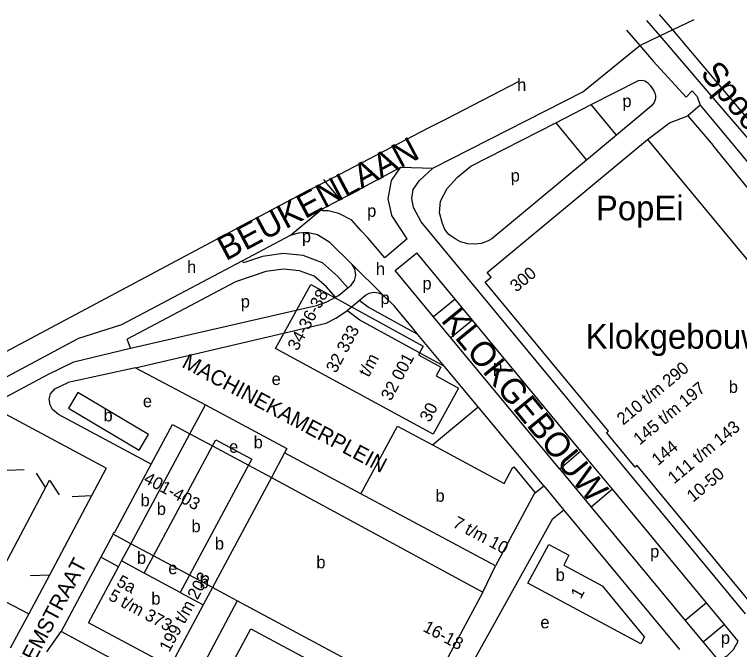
# Model space of a CAD drawing. Extents: x 159261 to 160849, y 382514 to 384534.
# Drawn here: x 159684.3 to 159920.1, y 384327.5 to 384534 of the extents above; entities that cross this region are included whole.
import ezdxf

# ---------------------------------------------------------------- set-up
doc = ezdxf.new("R2010")
doc.units = 0
for name, color, linetype in [('BLT_Basislijn', 7, 'Continuous'), ('BLT_Bebouwing', 7, 'Continuous'), ('BLT_Bebouwing_beschrifting', 7, 'Continuous'), ('BLT_Centroide', 7, 'Continuous'), ('BLT_Huisnummer', 7, 'Continuous'), ('BLT_Huisnummer_reeks', 7, 'Continuous'), ('BLT_Huisnummer_zonder_bebouwing', 7, 'Continuous'), ('BLT_Onderdoorgang_en_onderverdeling', 7, 'Continuous'), ('BLT_Plantopo', 7, 'Continuous'), ('BLT_Spoorlijn', 7, 'Continuous'), ('BLT_Straatnaam', 7, 'Continuous'), ('BLT_Straatnaam_hoofdweg', 7, 'Continuous'), ('BLT_Vlakafsluiter', 7, 'Continuous'), ('BLT_Waternaam_spoorwegen', 7, 'Continuous')]:
    doc.layers.add(name, color=color, linetype=linetype)

msp = doc.modelspace()

# ---------------------------------------------------------------- linework, layer by layer
at = {"layer": 'BLT_Basislijn'}
for p, q in [((159883.3, 384528.96), (159887.62, 384523.99)), ((159887.62, 384523.99), (159888.83, 384522.59)), ((159888.83, 384522.59), (159892.14, 384518.77)), ((159880.06, 384494.81), (159871.83, 384504.71)), ((159907.31, 384504.59), (159903.26, 384501.09)), ((159818.97, 384497.14), (159824.51, 384500)), ((159903.26, 384501.09), (159911.54, 384491.41)), ((159860.3, 384498.83), (159870.32, 384486.71)), ((159890.13, 384493.38), (159897.29, 384498.77)), ((159992.65, 384391.11), (159911.54, 384491.41)), ((159812, 384461.06), (159807.01, 384468.71)), ((159773.89, 384462.18), (159758.39, 384453.97)), ((159812, 384461.06), (159804.69, 384454.93)), ((159808.04, 384450.73), (159815.18, 384456.48)), ((159758.39, 384453.97), (159719.12, 384433.16)), ((159756.13, 384447.11), (159720.88, 384428.43)), ((159807.85, 384439.21), (159804.11, 384442.9)), ((159792.42, 384437.79), (159796.34, 384441.01)), ((159827.63, 384441.43), (159820.56, 384435.66)), ((159813.7, 384432.18), (159807.85, 384439.21)), ((159719.12, 384433.16), (159704.82, 384428.52)), ((159833.28, 384434.61), (159826.21, 384428.85)), ((159815.5, 384430), (159813.7, 384432.18)), ((159721.97, 384425.49), (159720.88, 384428.43)), ((159824.16, 384419.58), (159815.5, 384430)), ((159723.61, 384419.14), (159701.77, 384414.33)), ((159723.61, 384419.14), (159746.36, 384407.13)), ((159835.03, 384406.49), (159824.16, 384419.58)), ((159820.19, 384394.08), (159835.03, 384406.49)), ((159856.39, 384380.76), (159835.03, 384406.49)), ((159714.14, 384386.52), (159681.37, 384404.11)), ((159796.96, 384378.15), (159772.09, 384391.47)), ((159868.52, 384392.02), (159861.67, 384386.16)), ((159681.86, 384385.8), (159687.42, 384386.08)), ((159714.14, 384386.52), (159709.34, 384377.49)), ((159691.37, 384384.93), (159694.31, 384380.06)), ((159878.72, 384379.69), (159871.87, 384373.84)), ((159709.34, 384377.49), (159695.62, 384351.7)), ((159709.34, 384377.49), (159703.07, 384377.2)), ((159716.34, 384365.05), (159712.39, 384357.56)), ((159712.39, 384357.56), (159711.63, 384356.15)), ((159718.12, 384354.46), (159712.39, 384357.56)), ((159711.63, 384356.15), (159699.41, 384333.4)), ((159659.71, 384354.41), (159688.92, 384339.09)), ((159836.63, 384346.17), (159840.7, 384354.72)), ((159695.62, 384351.7), (159688.92, 384339.09)), ((159695.62, 384351.7), (159689.42, 384351.51)), ((159756.68, 384343.41), (159739.89, 384311.64)), ((159909.34, 384342.69), (159902.45, 384336.95)), ((159688.92, 384339.09), (159682.9, 384327.94)), ((159915.17, 384335.64), (159908.3, 384329.89)), ((159694.8, 384326.79), (159699.41, 384333.4)), ((159739.89, 384311.64), (159699.41, 384333.4))]:
    msp.add_line(p, q, dxfattribs=at)
for points in [[(159820.29, 384484.04), (159869.1, 384508.93), (159887.62, 384523.99)], [(159892.14, 384518.77), (159902.68, 384507.17), (159904.71, 384509.2), (159906.26, 384507.41), (159907.31, 384504.59)], [(159824.51, 384500), (159848.42, 384512.35)], [(159871.83, 384504.71), (159887.27, 384512.58)], [(159887.27, 384512.58), (159888.36, 384512.68), (159889.31, 384512.43), (159890.16, 384511.89), (159890.98, 384510.99), (159892.06, 384509.44), (159892.55, 384508.43), (159892.7, 384507.6), (159892.7, 384506.8), (159892.58, 384506.05), (159892.3, 384505.39), (159891.33, 384504.18), (159880.06, 384494.81)], [(159860.3, 384498.83), (159871.83, 384504.71)], [(159907.31, 384504.59), (159911.11, 384500)], [(159911.11, 384500), (159915.56, 384494.64)], [(159785.34, 384479.66), (159818.97, 384497.14)], [(159832.66, 384484.74), (159860.3, 384498.83)], [(159880.06, 384494.81), (159870.32, 384486.71)], [(159915.56, 384494.64), (159942.2, 384462.5), (159986.64, 384408.89), (159997.83, 384395.4)], [(159870.32, 384486.71), (159839.52, 384461.11), (159838.72, 384460.63), (159837.6, 384460.11), (159836.05, 384459.6), (159834.12, 384459.32), (159831.67, 384459.42), (159829.36, 384460.05), (159827.62, 384461.06), (159825.58, 384462.53), (159824.28, 384464.07), (159823.44, 384466.11), (159822.51, 384469.48), (159822.79, 384473.34), (159824.96, 384477.49), (159828.31, 384481.17), (159832.66, 384484.74)], [(159790.15, 384473.89), (159809.93, 384484.37)], [(159807.01, 384468.71), (159806.99, 384468.74), (159805.82, 384474.06), (159806.9, 384480.06), (159809.93, 384484.37)], [(159823.77, 384457.87), (159816.51, 384466.64), (159814.1, 384471.31), (159813.47, 384474.2), (159813.99, 384477.11), (159816.02, 384480), (159820.29, 384484.04)], [(159660.14, 384413.06), (159774.28, 384473.91), (159785.34, 384479.66)], [(159784.19, 384470.73), (159790.15, 384473.89)], [(159797.08, 384463.72), (159793.96, 384467.17), (159789.78, 384469.33), (159786.25, 384470.18), (159784.52, 384470.18), (159784.19, 384470.73)], [(159804.69, 384454.93), (159799.3, 384461.26), (159797.08, 384463.72)], [(159779.37, 384463.11), (159776.51, 384462.93), (159773.89, 384462.18)], [(159794.14, 384452.72), (159786.83, 384459.92), (159782.87, 384462.33), (159779.37, 384463.11)], [(159827.63, 384441.43), (159815.18, 384456.48)], [(159922.02, 384339.13), (159823.77, 384457.87)], [(159792.65, 384445.12), (159789.28, 384448.98), (159784.4, 384453.31), (159778.14, 384455.63), (159771.67, 384456.29), (159764.92, 384455.38), (159758.75, 384453.28), (159758.39, 384453.97)], [(159792.65, 384445.12), (159793.73, 384446.02), (159794.88, 384447.57), (159795.28, 384449.29), (159795.01, 384451.27), (159794.14, 384452.72)], [(159788.65, 384442.1), (159785.72, 384445.45), (159781.79, 384448.95), (159777, 384450.72), (159771.75, 384451.26), (159766.07, 384450.49), (159756.13, 384447.11)], [(159820.56, 384435.66), (159808.04, 384450.73)], [(159788.65, 384442.1), (159789.65, 384442.64), (159792.65, 384445.12)], [(159796.34, 384441.01), (159798.45, 384442.75), (159799.67, 384443.43), (159801.15, 384443.73), (159802.61, 384443.57), (159804.11, 384442.9)], [(159721.97, 384425.49), (159782.48, 384439.42), (159785.82, 384440.58), (159788.65, 384442.1)], [(159815.5, 384430), (159799.27, 384438.86), (159796.34, 384441.01)], [(159833.28, 384434.61), (159827.63, 384441.43)], [(159723.61, 384419.14), (159785.69, 384433.68), (159788.75, 384435.28), (159791.64, 384437.15), (159792.42, 384437.79)], [(159824.16, 384419.58), (159796.59, 384434.63), (159792.67, 384437.51), (159792.42, 384437.79)], [(159826.21, 384428.85), (159820.56, 384435.66)], [(159868.52, 384392.02), (159833.28, 384434.61)], [(159662.21, 384405.78), (159704.82, 384428.52)], [(159861.67, 384386.16), (159826.21, 384428.85)], [(159579.36, 384354.97), (159695.11, 384417), (159703.57, 384421.08), (159721.97, 384425.49)], [(159728.73, 384387.76), (159698.64, 384403.92), (159696.65, 384405.62), (159695.92, 384407.15), (159695.6, 384408.95), (159696.04, 384410.72), (159697.35, 384412.25), (159701.77, 384414.33)], [(159878.72, 384379.69), (159868.52, 384392.02)], [(159861.67, 384386.15), (159871.87, 384373.84)], [(159680.99, 384354.8), (159695.68, 384382.55), (159698.84, 384377.82)], [(159853.65, 384378.49), (159856.39, 384380.76)], [(159909.34, 384342.69), (159878.72, 384379.69)], [(159862.97, 384372.83), (159859.15, 384369.78), (159831.21, 384319.52)], [(159862.97, 384372.83), (159900.54, 384327.5)], [(159871.87, 384373.84), (159902.45, 384336.95)], [(159915.17, 384335.64), (159909.34, 384342.69)], [(159902.45, 384336.95), (159908.3, 384329.89)], [(159919.61, 384330.28), (159915.17, 384335.64)], [(159908.3, 384329.89), (159913.1, 384324.1)], [(159913.1, 384324.1), (159916.05, 384325.43), (159918.17, 384327.51), (159919.61, 384330.28)]]:
    msp.add_lwpolyline(points, dxfattribs=at)
at = {"layer": 'BLT_Bebouwing'}
for p, q in [((159741.29, 384397.67), (159746.36, 384407.13)), ((159728.73, 384387.76), (159735.7, 384400.71)), ((159735.7, 384400.71), (159741.29, 384397.67)), ((159722.1, 384361.89), (159741.29, 384397.67)), ((159729.46, 384357.96), (159748.69, 384393.74)), ((159748.69, 384393.74), (159760.41, 384387.46)), ((159772.09, 384391.47), (159767.81, 384383.48)), ((159760.41, 384387.46), (159741.21, 384351.68)), ((159767.81, 384383.48), (159748.65, 384347.7)), ((159767.81, 384383.48), (159836.63, 384346.17)), ((159722.1, 384361.89), (159716.34, 384365.05)), ((159719.11, 384356.32), (159722.1, 384361.89)), ((159726.46, 384352.38), (159729.46, 384357.96)), ((159741.21, 384351.68), (159729.46, 384357.96)), ((159718.12, 384354.46), (159719.11, 384356.32)), ((159738.21, 384346.1), (159726.46, 384352.38)), ((159741.21, 384351.68), (159738.21, 384346.1)), ((159889.19, 384331.68), (159875.6, 384348.17)), ((159748.65, 384347.7), (159745.65, 384342.11)), ((159756.68, 384343.41), (159748.65, 384347.7)), ((159836.63, 384346.17), (159817.59, 384310.79)), ((159817.59, 384310.79), (159756.68, 384343.41)), ((159745.65, 384342.11), (159744.63, 384340.2))]:
    msp.add_line(p, q, dxfattribs=at)
for points in [[(159837.38, 384446.95), (159839.29, 384448.56), (159837.99, 384450.14), (159890.13, 384493.38)], [(159890.13, 384493.38), (159982.21, 384382.41)], [(159928.03, 384337.56), (159886.79, 384387.35), (159886.17, 384386.84), (159876.87, 384398.07), (159877.5, 384398.55), (159837.38, 384446.95)], [(159746.36, 384407.13), (159772.85, 384392.87), (159772.09, 384391.47)], [(159840.7, 384354.72), (159796.96, 384378.15), (159808.8, 384400.21)], [(159808.8, 384400.21), (159820.19, 384394.08)], [(159748.69, 384393.74), (159749.76, 384395.71), (159761.46, 384389.44), (159760.41, 384387.46)], [(159820.19, 384394.08), (159843.58, 384381.5), (159846.26, 384386.64), (159846.65, 384386.97), (159853.65, 384378.49)], [(159716.34, 384365.05), (159716.72, 384365.76), (159716.86, 384365.69), (159728.73, 384387.76)], [(159853.65, 384378.49), (159853.29, 384378.19), (159840.7, 384354.72)], [(159851.21, 384349.09), (159858.11, 384361.67), (159864.61, 384358.17), (159862.89, 384354.97), (159875.6, 384348.17)], [(159744.63, 384340.2), (159734.86, 384321.96), (159708.32, 384336.18), (159718.12, 384354.46)], [(159889.19, 384331.68), (159887.99, 384329.43), (159851.21, 384349.09)]]:
    msp.add_lwpolyline(points, dxfattribs=at)
msp.add_lwpolyline([(159704.88, 384411.09), (159701.85, 384405.99), (159724.8, 384392.36), (159727.83, 384397.47)], close=True, dxfattribs=at)
at = {"layer": 'BLT_Onderdoorgang_en_onderverdeling'}
for p, q in [((159741.29, 384397.67), (159748.69, 384393.74)), ((159760.41, 384387.46), (159767.81, 384383.48)), ((159729.46, 384357.96), (159722.1, 384361.89)), ((159726.46, 384352.38), (159719.11, 384356.32)), ((159748.65, 384347.7), (159741.21, 384351.68)), ((159738.21, 384346.1), (159745.65, 384342.11))]:
    msp.add_line(p, q, dxfattribs=at)
at = {"layer": 'BLT_Plantopo'}
for points in [[(159769.19, 384425.37), (159780.61, 384446.25), (159817.23, 384426.21), (159815.69, 384423.4), (159822.99, 384419.4), (159821.41, 384416.51), (159828.65, 384412.55), (159820.48, 384397.52)], [(159761.12, 384334.25), (159813.05, 384306.37), (159801.06, 384284.04), (159749.13, 384311.92)]]:
    msp.add_lwpolyline(points, close=True, dxfattribs=at)
at = {"layer": 'BLT_Spoorlijn'}
for p, q in [((159889.83, 384532.07), (159894.12, 384527.06)), ((159898.24, 384529.01), (159922.83, 384500)), ((159894.12, 384527.06), (159915.97, 384501.58))]:
    msp.add_line(p, q, dxfattribs=at)
for points in [[(159893.95, 384534.03), (159896.83, 384530.68), (159898.24, 384529.01)], [(159915.97, 384501.58), (159917.34, 384500)], [(159917.34, 384500), (159975.81, 384432.34)]]:
    msp.add_lwpolyline(points, dxfattribs=at)
at = {"layer": 'BLT_Vlakafsluiter'}
for p, q in [((159898.24, 384529.01), (159905.34, 384532.37)), ((159894.12, 384527.06), (159898.24, 384529.01)), ((159887.62, 384523.99), (159894.12, 384527.06)), ((159897.29, 384498.77), (159903.26, 384501.09)), ((159809.93, 384484.37), (159820.29, 384484.04)), ((159784.77, 384480.36), (159785.34, 384479.66)), ((159785.34, 384479.66), (159790.15, 384473.89)), ((159773.89, 384462.18), (159784.19, 384470.73)), ((159804.11, 384442.9), (159794.14, 384452.72))]:
    msp.add_line(p, q, dxfattribs=at)
msp.add_lwpolyline([(159856.39, 384380.76), (159862.97, 384372.83)], dxfattribs=at)

# ---------------------------------------------------------------- texts
at = {"layer": 'BLT_Bebouwing_beschrifting'}
for s, p in [('PopEi', (159873.36, 384467.11)), ('Klokgebouw', (159870.05, 384425.34))]:
    msp.add_text(s, height=8, dxfattribs=at).set_placement(p)
at = {"layer": 'BLT_Centroide'}
for s, p in [('h', (159847.75, 384509.18)), ('p', (159798.97, 384468.22)), ('h', (159740.4, 384449.93)), ('h', (159801.82, 384449.32)), ('p', (159816.95, 384444.62)), ('p', (159803.31, 384439.87)), ('p', (159839.92, 384417.64)), ('e', (159767.91, 384413.54)), ('b', (159916.6, 384410.98)), ('e', (159726.03, 384406.34)), ('b', (159713.24, 384401.71)), ('b', (159762.06, 384392.96)), ('e', (159754.08, 384391.51)), ('b', (159821.21, 384375.56)), ('b', (159725.29, 384374.08)), ('b', (159730.57, 384371.3)), ('b', (159741.84, 384365.67)), ('b', (159749.45, 384360.03)), ('p', (159891, 384357.46)), ('b', (159724.12, 384355.38)), ('b', (159782.45, 384353.95)), ('e', (159734.29, 384352.02)), ('b', (159860.29, 384349.82)), ('b', (159744.49, 384347.43)), ('b', (159728.79, 384342.14)), ('e', (159855.32, 384334.43)), ('p', (159914.02, 384329.36))]:
    msp.add_text(s, height=4, dxfattribs=at).set_placement(p)
for p in [(159882.02, 384503.9), (159845.68, 384479.67), (159777.78, 384459.92), (159757.89, 384438.7)]:
    msp.add_text('p', height=4, rotation=1, dxfattribs=at).set_placement(p)
at = {"layer": 'BLT_Huisnummer'}
msp.add_text('1', height=4, rotation=61.8407, dxfattribs=at).set_placement((159868.43, 384343.73))
at = {"layer": 'BLT_Huisnummer_reeks'}
for s, rotation, p in [('300', 39.7499, (159847.49, 384443.54)), ('210 t/m 290', 39.7499, (159882.24, 384400.32)), ('145 t/m 197', 39.6073, (159887.57, 384393.81)), ('111 t/m 143', 39.6073, (159898.82, 384381.22)), ('144', 39.6073, (159893.55, 384387.14)), ('10-50', 39.7499, (159904.98, 384375.26)), ('401-403', 331.8407, (159725.97, 384381.94)), ('7 t/m 10', 331.8407, (159826.49, 384367.55)), ('5a', 331.7488, (159717.18, 384348.46)), ('199 t/m 203', 61.7488, (159734.62, 384326.43)), ('5 t/m 373', 331.7488, (159714.53, 384343.85)), ('16-18', 331.8407, (159816.82, 384333.66))]:
    msp.add_text(s, height=4, rotation=rotation, dxfattribs=at).set_placement(p)
at = {"layer": 'BLT_Huisnummer_zonder_bebouwing'}
for s, p in [('34-36-38', (159776.33, 384424.42)), ('32 333', (159788.84, 384417.18)), ('32 001', (159806.69, 384408.14)), ('t/m', (159799.46, 384415.83)), ('30', (159819.31, 384401.16))]:
    msp.add_text(s, height=4, rotation=61.8407, dxfattribs=at).set_placement(p)
at = {"layer": 'BLT_Straatnaam'}
for s, rotation, p in [('MACHINEKAMERPLEIN', 331.9651, (159738.39, 384419.55)), ('VEEMSTRAAT', 61.9651, (159686.67, 384315.48))]:
    msp.add_text(s, height=5, rotation=rotation, dxfattribs=at).set_placement(p)
at = {"layer": 'BLT_Straatnaam_hoofdweg'}
for s, rotation, p in [('BEUKENLAAN', 27.9501, (159753, 384453.78)), ('KLOKGEBOUW', 309.279, (159822.72, 384434.45))]:
    msp.add_text(s, height=8, rotation=rotation, dxfattribs=at).set_placement(p)
at = {"layer": 'BLT_Waternaam_spoorwegen'}
msp.add_text('Spoorlijn', height=8, rotation=309.5774, dxfattribs=at).set_placement((159907.03, 384514.7))

doc.saveas('drawing.dxf')
